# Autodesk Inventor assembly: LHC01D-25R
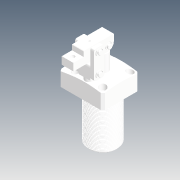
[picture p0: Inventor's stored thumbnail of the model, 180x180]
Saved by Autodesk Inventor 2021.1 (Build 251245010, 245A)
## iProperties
Created: 2019-04
Part Number: LHC01D-25R
Description: STEP AP214
Document SubType Name: Assembly
Designer: user
Title: LHC01D-25R.STEP
Revision Number: ÈÎºÎ
Sending System: SolidWorks 2016
Preprocessor: SwSTEP 2.0
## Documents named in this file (12)
- D:\Vault_2016\Projekty\Clamptek\Hydraulic\LHC01D\Inventor\LHC01D-25R\LHC01D-25R.iam
- D:\Vault_2016\Projekty\Clamptek\Hydraulic\LHC01D\Inventor\LHC01D-25R\LHC01D-25-01_2.ipt
- D:\Vault_2016\Projekty\Clamptek\Hydraulic\LHC01D\Inventor\LHC01D-25R\CPLCU-25-01_2.ipt
- D:\Vault_2016\Projekty\Clamptek\Hydraulic\LHC01D\Inventor\LHC01D-25R\CPLCU-25-02_2.ipt
- D:\Vault_2016\Projekty\Clamptek\Hydraulic\LHC01D\Inventor\LHC01D-25R\CPLCU-25-03_2.ipt
- D:\Vault_2016\Projekty\Clamptek\Hydraulic\LHC01D\Inventor\LHC01D-25R\CPLCU-25-04_2.ipt
- D:\Vault_2016\Projekty\Clamptek\Hydraulic\LHC01D\Inventor\LHC01D-25R\CPLCU-25-05_2.ipt
- D:\Vault_2016\Projekty\Clamptek\Hydraulic\LHC01D\Inventor\LHC01D-25R\LHC01D25»îÈû¸Ë.ipt
- D:\Vault_2016\Projekty\Clamptek\Hydraulic\LHC01D\Inventor\LHC01D-25R\CPLCU-25-09_2.ipt
- D:\Vault_2016\Projekty\Clamptek\Hydraulic\LHC01D\Inventor\LHC01D-25R\LHC01D-32-01_2.ipt
- D:\Vault_2016\Projekty\Clamptek\Hydraulic\LHC01D\Inventor\LHC01D-25R\M4ningjin_2.ipt
- D:\Vault_2016\Projekty\Clamptek\Hydraulic\LHC01D\Inventor\LHC01D-25R\¶ÂÍ·_2.ipt
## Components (23 placed, 23 different names)
1. LHC01D-25-01_2_1
2. CPLCU-25-01_2_2
3. CPLCU-25-02_2_3
4. CPLCU-25-03_2_4
5. CPLCU-25-04_2_5
6. CPLCU-25-05_2_6
7. LHC01D25»îÈû¸Ë_7
8. CPLCU-25-09_2_8
9. LHC01D-32-01_2_9
10. CPLCU-25-02_2_10
11. CPLCU-25-09_2_11
12. CPLCU-25-09_2_12
13. CPLCU-25-09_2_13
14. CPLCU-25-09_2_14
15. CPLCU-25-09_2_15
16. CPLCU-25-04_2_16
17. LHC01D-32-01_2_17
18. LHC01D-32-01_2_18
19. LHC01D-32-01_2_19
20. LHC01D-32-01_2_20
21. M4ningjin_2_21
22. ¶ÂÍ·_2_22
23. ¶ÂÍ·_2_23
